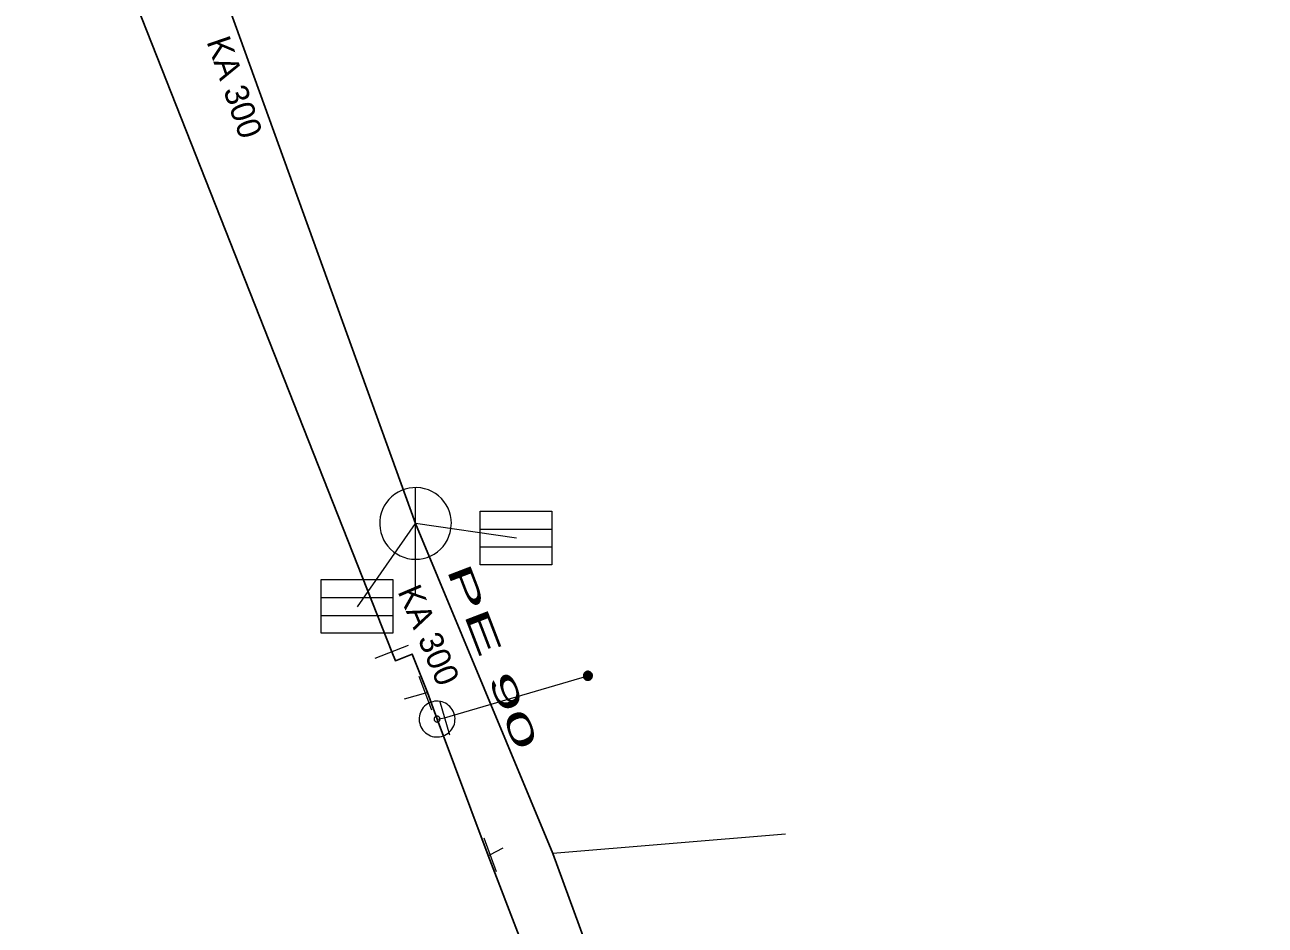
# Model space of a CAD drawing. Extents: x -688432 to -687974, y -973332 to -972704.
# Drawn here: x -688249.47 to -688214.87, y -972930.31 to -972905.19 of the extents above; entities that cross this region are included whole.
import ezdxf
from ezdxf.enums import TextEntityAlignment as Align

# ---------------------------------------------------------------- set-up
doc = ezdxf.new("R2010")
doc.units = 0
doc.header["$LTSCALE"] = 0.27
for name, color, linetype, lineweight in [('1', 7, 'Continuous', 25), ('11', 7, 'Continuous', 13), ('13', 7, 'Continuous', 13), ('14', 7, 'Continuous', 25), ('17', 7, 'Continuous', 25), ('22', 7, 'Continuous', 13), ('34', 7, 'Continuous', 13), ('47', 7, 'Continuous', 13), ('9', 7, 'Continuous', 13)]:
    doc.layers.add(name, color=color, linetype=linetype, lineweight=lineweight)

msp = doc.modelspace()

# ---------------------------------------------------------------- linework, layer by layer
at = {"layer": '11'}
for p, q in [((-688240.193, -972921.423), (-688238.57, -972919.1)), ((-688235.756, -972919.514), (-688238.57, -972919.1)), ((-688228.249, -972927.769), (-688234.738, -972928.309))]:
    msp.add_line(p, q, dxfattribs=at)
at = {"layer": '13'}
for p, q in [((-688238.292, -972923.84), (-688238.89, -972924)), ((-688236.494, -972928.343), (-688236.129, -972928.149))]:
    msp.add_line(p, q, dxfattribs=at)
at = {"layer": '14'}
msp.add_line((-688238.57, -972919.1), (-688245.539, -972899.801), dxfattribs=at)
at = {"layer": '14', "lineweight": 13}
for p, q in [((-688238.239, -972923.82), (-688238.292, -972923.84)), ((-688236.539, -972928.36), (-688236.494, -972928.343))]:
    msp.add_line(p, q, dxfattribs=at)
at = {"layer": '14'}
msp.add_lwpolyline([(-688232.039, -972935.68), (-688234.738, -972928.309), (-688238.57, -972919.1)], dxfattribs=at)
at = {"layer": '14', "lineweight": 13}
msp.add_lwpolyline([(-688237.969, -972924.559), (-688237.76, -972924.52), (-688233.76, -972923.35)], dxfattribs=at)
at = {"layer": '17'}
for points in [[(-688239.23, -972922.68), (-688246.472, -972904.316), (-688249.47, -972882.184)], [(-688237.969, -972924.559), (-688238.239, -972923.82), (-688238.659, -972922.743), (-688239.129, -972922.93), (-688239.23, -972922.68)], [(-688167.42, -973053.719), (-688175.149, -973043.51), (-688175.68, -973042.93), (-688189.18, -973023.62), (-688194.239, -973015.879), (-688201.127, -973004.614), (-688201.64, -973003.76), (-688208.85, -972990.539), (-688214.25, -972980.469), (-688218.649, -972971.53), (-688218.84, -972971.059), (-688222.559, -972963.52), (-688226.68, -972954.28), (-688230.09, -972945.899), (-688231.09, -972942.949), (-688233.719, -972935.719), (-688236.539, -972928.36), (-688237.969, -972924.559)]]:
    msp.add_lwpolyline(points, dxfattribs=at)
at = {"layer": '22'}
for p, q in [((-688238.57, -972921.1), (-688238.569, -972918.1)), ((-688236.767, -972919.257), (-688234.767, -972919.257)), ((-688236.767, -972919.757), (-688234.767, -972919.757)), ((-688241.204, -972921.166), (-688239.204, -972921.166)), ((-688241.204, -972921.666), (-688239.204, -972921.666))]:
    msp.add_line(p, q, dxfattribs=at)
for points in [[(-688237.57, -972919.1), (-688237.575, -972918.991), (-688237.593, -972918.883), (-688237.623, -972918.777), (-688237.663, -972918.676), (-688237.715, -972918.579), (-688237.777, -972918.489), (-688237.849, -972918.406), (-688237.929, -972918.332), (-688238.017, -972918.266), (-688238.111, -972918.211), (-688238.211, -972918.166), (-688238.316, -972918.133), (-688238.423, -972918.111), (-688238.532, -972918.101), (-688238.642, -972918.103), (-688238.75, -972918.117), (-688238.857, -972918.142), (-688238.96, -972918.179), (-688239.058, -972918.228), (-688239.15, -972918.286), (-688239.236, -972918.355), (-688239.313, -972918.432), (-688239.382, -972918.518), (-688239.441, -972918.61), (-688239.489, -972918.708), (-688239.526, -972918.811), (-688239.552, -972918.918), (-688239.566, -972919.026), (-688239.569, -972919.136), (-688239.559, -972919.245), (-688239.538, -972919.352), (-688239.504, -972919.456), (-688239.46, -972919.556), (-688239.405, -972919.651), (-688239.339, -972919.739), (-688239.265, -972919.819), (-688239.182, -972919.891), (-688239.092, -972919.953), (-688238.996, -972920.005), (-688238.894, -972920.046), (-688238.789, -972920.076), (-688238.681, -972920.094), (-688238.571, -972920.1), (-688238.462, -972920.094), (-688238.354, -972920.076), (-688238.249, -972920.047), (-688238.147, -972920.006), (-688238.05, -972919.954), (-688237.96, -972919.892), (-688237.877, -972919.821), (-688237.802, -972919.741), (-688237.737, -972919.653), (-688237.681, -972919.559), (-688237.637, -972919.459), (-688237.603, -972919.355), (-688237.581, -972919.247), (-688237.571, -972919.138)], [(-688236.767, -972918.757), (-688234.767, -972918.757), (-688234.767, -972920.257), (-688236.767, -972920.257)], [(-688241.204, -972920.666), (-688239.204, -972920.666), (-688239.204, -972922.166), (-688241.204, -972922.166)]]:
    msp.add_lwpolyline(points, close=True, dxfattribs=at)
at = {"layer": '34'}
for p, q in [((-688239.694, -972922.863), (-688238.764, -972922.497)), ((-688238.112, -972924.306), (-688238.47, -972923.373)), ((-688237.9, -972924.04), (-688237.62, -972925)), ((-688236.666, -972927.873), (-688236.322, -972928.812))]:
    msp.add_line(p, q, dxfattribs=at)
at = {"layer": '47'}
for points in [[(-688238.14, -972924.089), (-688238.188, -972924.109), (-688238.234, -972924.135), (-688238.276, -972924.165), (-688238.316, -972924.199), (-688238.352, -972924.237), (-688238.383, -972924.28), (-688238.409, -972924.324), (-688238.432, -972924.372), (-688238.449, -972924.421), (-688238.461, -972924.472), (-688238.467, -972924.524), (-688238.468, -972924.577), (-688238.464, -972924.628), (-688238.453, -972924.68), (-688238.438, -972924.73), (-688238.418, -972924.778), (-688238.392, -972924.824), (-688238.362, -972924.867), (-688238.328, -972924.906), (-688238.29, -972924.942), (-688238.247, -972924.973), (-688238.202, -972925), (-688238.155, -972925.022), (-688238.106, -972925.04), (-688238.055, -972925.051), (-688238.003, -972925.057), (-688237.95, -972925.058), (-688237.899, -972925.054), (-688237.847, -972925.043), (-688237.797, -972925.028), (-688237.749, -972925.008), (-688237.703, -972924.982), (-688237.66, -972924.953), (-688237.621, -972924.918), (-688237.585, -972924.88), (-688237.553, -972924.838), (-688237.526, -972924.793), (-688237.504, -972924.746), (-688237.487, -972924.696), (-688237.476, -972924.645), (-688237.47, -972924.593), (-688237.468, -972924.541), (-688237.473, -972924.489), (-688237.484, -972924.437), (-688237.499, -972924.387), (-688237.519, -972924.339), (-688237.545, -972924.293), (-688237.574, -972924.251), (-688237.609, -972924.211), (-688237.647, -972924.175), (-688237.689, -972924.143), (-688237.734, -972924.117), (-688237.781, -972924.095), (-688237.831, -972924.078), (-688237.882, -972924.066), (-688237.934, -972924.06), (-688237.986, -972924.059), (-688238.038, -972924.063), (-688238.09, -972924.074)], [(-688237.997, -972924.481), (-688238.005, -972924.485), (-688238.012, -972924.489), (-688238.019, -972924.494), (-688238.025, -972924.499), (-688238.031, -972924.506), (-688238.036, -972924.513), (-688238.041, -972924.52), (-688238.045, -972924.528), (-688238.047, -972924.536), (-688238.049, -972924.544), (-688238.05, -972924.553), (-688238.05, -972924.562), (-688238.049, -972924.57), (-688238.049, -972924.578), (-688238.046, -972924.587), (-688238.042, -972924.595), (-688238.038, -972924.602), (-688238.033, -972924.609), (-688238.028, -972924.615), (-688238.021, -972924.621), (-688238.014, -972924.626), (-688238.007, -972924.631), (-688237.999, -972924.635), (-688237.991, -972924.638), (-688237.983, -972924.639), (-688237.974, -972924.64), (-688237.965, -972924.64), (-688237.957, -972924.639), (-688237.949, -972924.639), (-688237.94, -972924.636), (-688237.932, -972924.632), (-688237.925, -972924.628), (-688237.918, -972924.623), (-688237.912, -972924.618), (-688237.906, -972924.611), (-688237.9, -972924.605), (-688237.896, -972924.597), (-688237.892, -972924.589), (-688237.889, -972924.581), (-688237.888, -972924.573), (-688237.887, -972924.564), (-688237.887, -972924.555), (-688237.888, -972924.547), (-688237.888, -972924.539), (-688237.891, -972924.53), (-688237.895, -972924.522), (-688237.899, -972924.515), (-688237.904, -972924.508), (-688237.909, -972924.502), (-688237.916, -972924.496), (-688237.922, -972924.49), (-688237.93, -972924.486), (-688237.938, -972924.482), (-688237.946, -972924.48), (-688237.954, -972924.478), (-688237.963, -972924.477), (-688237.972, -972924.477), (-688237.98, -972924.478), (-688237.988, -972924.478)]]:
    msp.add_lwpolyline(points, close=True, dxfattribs=at)
at = {"layer": '9'}
for points in [[(-688233.886, -972923.35), (-688233.886, -972923.363), (-688233.884, -972923.376), (-688233.881, -972923.389), (-688233.876, -972923.401), (-688233.87, -972923.413), (-688233.863, -972923.424), (-688233.855, -972923.434), (-688233.845, -972923.444), (-688233.835, -972923.452), (-688233.824, -972923.459), (-688233.812, -972923.465), (-688233.8, -972923.47), (-688233.787, -972923.473), (-688233.774, -972923.475), (-688233.761, -972923.477), (-688233.748, -972923.476), (-688233.735, -972923.474), (-688233.722, -972923.471), (-688233.71, -972923.466), (-688233.698, -972923.46), (-688233.687, -972923.453), (-688233.677, -972923.445), (-688233.667, -972923.435), (-688233.659, -972923.425), (-688233.652, -972923.414), (-688233.646, -972923.402), (-688233.641, -972923.39), (-688233.638, -972923.377), (-688233.636, -972923.364), (-688233.634, -972923.351), (-688233.635, -972923.338), (-688233.637, -972923.325), (-688233.64, -972923.312), (-688233.645, -972923.3), (-688233.651, -972923.288), (-688233.658, -972923.277), (-688233.666, -972923.267), (-688233.676, -972923.257), (-688233.686, -972923.249), (-688233.697, -972923.242), (-688233.709, -972923.236), (-688233.721, -972923.231), (-688233.734, -972923.228), (-688233.747, -972923.226), (-688233.76, -972923.225), (-688233.773, -972923.225), (-688233.786, -972923.227), (-688233.799, -972923.23), (-688233.811, -972923.235), (-688233.823, -972923.241), (-688233.834, -972923.248), (-688233.844, -972923.256), (-688233.854, -972923.266), (-688233.862, -972923.276), (-688233.869, -972923.287), (-688233.875, -972923.299), (-688233.88, -972923.311), (-688233.883, -972923.324), (-688233.885, -972923.337)], [(-688233.866, -972923.35), (-688233.867, -972923.361), (-688233.865, -972923.372), (-688233.862, -972923.383), (-688233.858, -972923.393), (-688233.853, -972923.403), (-688233.847, -972923.412), (-688233.84, -972923.421), (-688233.832, -972923.429), (-688233.823, -972923.436), (-688233.814, -972923.442), (-688233.804, -972923.447), (-688233.794, -972923.451), (-688233.783, -972923.454), (-688233.772, -972923.457), (-688233.761, -972923.457), (-688233.75, -972923.457), (-688233.739, -972923.455), (-688233.728, -972923.452), (-688233.718, -972923.448), (-688233.708, -972923.443), (-688233.699, -972923.437), (-688233.69, -972923.43), (-688233.682, -972923.422), (-688233.675, -972923.413), (-688233.669, -972923.404), (-688233.664, -972923.394), (-688233.66, -972923.384), (-688233.657, -972923.373), (-688233.655, -972923.362), (-688233.654, -972923.351), (-688233.654, -972923.34), (-688233.656, -972923.329), (-688233.659, -972923.318), (-688233.663, -972923.308), (-688233.668, -972923.298), (-688233.674, -972923.289), (-688233.681, -972923.28), (-688233.689, -972923.272), (-688233.698, -972923.265), (-688233.707, -972923.259), (-688233.717, -972923.254), (-688233.727, -972923.25), (-688233.738, -972923.247), (-688233.749, -972923.245), (-688233.76, -972923.245), (-688233.771, -972923.244), (-688233.782, -972923.246), (-688233.793, -972923.249), (-688233.803, -972923.253), (-688233.813, -972923.258), (-688233.822, -972923.264), (-688233.831, -972923.271), (-688233.839, -972923.279), (-688233.846, -972923.288), (-688233.852, -972923.297), (-688233.857, -972923.307), (-688233.861, -972923.317), (-688233.864, -972923.328), (-688233.866, -972923.339)], [(-688233.847, -972923.35), (-688233.847, -972923.359), (-688233.846, -972923.368), (-688233.843, -972923.377), (-688233.84, -972923.385), (-688233.836, -972923.393), (-688233.831, -972923.401), (-688233.825, -972923.408), (-688233.819, -972923.414), (-688233.812, -972923.42), (-688233.804, -972923.425), (-688233.796, -972923.429), (-688233.788, -972923.432), (-688233.779, -972923.435), (-688233.77, -972923.436), (-688233.761, -972923.438), (-688233.752, -972923.437), (-688233.743, -972923.436), (-688233.734, -972923.433), (-688233.726, -972923.43), (-688233.718, -972923.426), (-688233.71, -972923.421), (-688233.703, -972923.415), (-688233.697, -972923.409), (-688233.691, -972923.402), (-688233.686, -972923.394), (-688233.682, -972923.386), (-688233.679, -972923.378), (-688233.676, -972923.369), (-688233.675, -972923.36), (-688233.673, -972923.351), (-688233.674, -972923.342), (-688233.675, -972923.333), (-688233.678, -972923.324), (-688233.681, -972923.316), (-688233.685, -972923.308), (-688233.69, -972923.3), (-688233.696, -972923.293), (-688233.702, -972923.287), (-688233.709, -972923.281), (-688233.717, -972923.276), (-688233.725, -972923.272), (-688233.733, -972923.269), (-688233.742, -972923.266), (-688233.751, -972923.265), (-688233.76, -972923.264), (-688233.769, -972923.264), (-688233.778, -972923.265), (-688233.787, -972923.268), (-688233.795, -972923.271), (-688233.803, -972923.275), (-688233.811, -972923.28), (-688233.818, -972923.286), (-688233.824, -972923.292), (-688233.83, -972923.299), (-688233.835, -972923.307), (-688233.839, -972923.315), (-688233.842, -972923.323), (-688233.845, -972923.332), (-688233.846, -972923.341)], [(-688233.827, -972923.35), (-688233.827, -972923.357), (-688233.826, -972923.364), (-688233.825, -972923.371), (-688233.822, -972923.377), (-688233.819, -972923.383), (-688233.815, -972923.389), (-688233.811, -972923.395), (-688233.806, -972923.4), (-688233.8, -972923.404), (-688233.794, -972923.408), (-688233.788, -972923.411), (-688233.782, -972923.414), (-688233.775, -972923.415), (-688233.768, -972923.418), (-688233.761, -972923.418), (-688233.754, -972923.418), (-688233.747, -972923.416), (-688233.74, -972923.415), (-688233.734, -972923.412), (-688233.727, -972923.409), (-688233.722, -972923.405), (-688233.716, -972923.401), (-688233.711, -972923.396), (-688233.707, -972923.39), (-688233.703, -972923.384), (-688233.7, -972923.378), (-688233.697, -972923.372), (-688233.695, -972923.365), (-688233.694, -972923.358), (-688233.693, -972923.351), (-688233.693, -972923.344), (-688233.694, -972923.337), (-688233.696, -972923.33), (-688233.699, -972923.324), (-688233.702, -972923.317), (-688233.706, -972923.312), (-688233.71, -972923.306), (-688233.715, -972923.301), (-688233.721, -972923.297), (-688233.726, -972923.293), (-688233.733, -972923.29), (-688233.739, -972923.287), (-688233.746, -972923.285), (-688233.753, -972923.284), (-688233.76, -972923.284), (-688233.767, -972923.284), (-688233.774, -972923.284), (-688233.781, -972923.286), (-688233.787, -972923.289), (-688233.793, -972923.292), (-688233.799, -972923.296), (-688233.805, -972923.3), (-688233.81, -972923.305), (-688233.814, -972923.311), (-688233.818, -972923.316), (-688233.821, -972923.323), (-688233.824, -972923.329), (-688233.825, -972923.336), (-688233.827, -972923.343)], [(-688233.807, -972923.35), (-688233.807, -972923.355), (-688233.807, -972923.36), (-688233.806, -972923.365), (-688233.804, -972923.369), (-688233.802, -972923.374), (-688233.799, -972923.378), (-688233.796, -972923.381), (-688233.792, -972923.385), (-688233.789, -972923.388), (-688233.785, -972923.391), (-688233.78, -972923.393), (-688233.776, -972923.395), (-688233.771, -972923.396), (-688233.766, -972923.398), (-688233.761, -972923.398), (-688233.756, -972923.398), (-688233.751, -972923.397), (-688233.746, -972923.396), (-688233.742, -972923.394), (-688233.737, -972923.392), (-688233.733, -972923.389), (-688233.729, -972923.386), (-688233.726, -972923.382), (-688233.723, -972923.379), (-688233.72, -972923.375), (-688233.718, -972923.37), (-688233.716, -972923.366), (-688233.715, -972923.361), (-688233.714, -972923.356), (-688233.713, -972923.351), (-688233.713, -972923.346), (-688233.714, -972923.341), (-688233.715, -972923.336), (-688233.717, -972923.332), (-688233.719, -972923.327), (-688233.722, -972923.323), (-688233.725, -972923.319), (-688233.728, -972923.316), (-688233.732, -972923.313), (-688233.736, -972923.31), (-688233.741, -972923.308), (-688233.745, -972923.306), (-688233.75, -972923.305), (-688233.755, -972923.304), (-688233.76, -972923.304), (-688233.765, -972923.304), (-688233.77, -972923.305), (-688233.775, -972923.305), (-688233.779, -972923.307), (-688233.784, -972923.309), (-688233.788, -972923.312), (-688233.791, -972923.315), (-688233.795, -972923.318), (-688233.798, -972923.322), (-688233.801, -972923.326), (-688233.803, -972923.331), (-688233.805, -972923.335), (-688233.806, -972923.34), (-688233.807, -972923.345)], [(-688233.787, -972923.35), (-688233.787, -972923.353), (-688233.788, -972923.356), (-688233.787, -972923.358), (-688233.786, -972923.361), (-688233.785, -972923.364), (-688233.783, -972923.366), (-688233.781, -972923.368), (-688233.779, -972923.37), (-688233.777, -972923.372), (-688233.775, -972923.374), (-688233.772, -972923.376), (-688233.769, -972923.377), (-688233.767, -972923.377), (-688233.764, -972923.378), (-688233.761, -972923.378), (-688233.758, -972923.378), (-688233.755, -972923.378), (-688233.752, -972923.377), (-688233.75, -972923.376), (-688233.747, -972923.375), (-688233.745, -972923.373), (-688233.742, -972923.371), (-688233.74, -972923.369), (-688233.739, -972923.367), (-688233.737, -972923.365), (-688233.736, -972923.362), (-688233.734, -972923.359), (-688233.734, -972923.357), (-688233.733, -972923.354), (-688233.732, -972923.351), (-688233.733, -972923.348), (-688233.733, -972923.345), (-688233.734, -972923.342), (-688233.735, -972923.34), (-688233.736, -972923.337), (-688233.738, -972923.335), (-688233.739, -972923.332), (-688233.741, -972923.33), (-688233.744, -972923.329), (-688233.746, -972923.327), (-688233.749, -972923.326), (-688233.751, -972923.325), (-688233.754, -972923.324), (-688233.757, -972923.324), (-688233.76, -972923.323), (-688233.763, -972923.324), (-688233.766, -972923.323), (-688233.768, -972923.325), (-688233.771, -972923.325), (-688233.774, -972923.326), (-688233.776, -972923.328), (-688233.778, -972923.329), (-688233.78, -972923.331), (-688233.782, -972923.334), (-688233.784, -972923.336), (-688233.785, -972923.339), (-688233.786, -972923.341), (-688233.787, -972923.344), (-688233.787, -972923.347)], [(-688233.768, -972923.35), (-688233.768, -972923.352), (-688233.768, -972923.352), (-688233.767, -972923.352), (-688233.767, -972923.354), (-688233.768, -972923.355), (-688233.766, -972923.355), (-688233.766, -972923.355), (-688233.766, -972923.357), (-688233.766, -972923.357), (-688233.765, -972923.358), (-688233.763, -972923.358), (-688233.763, -972923.358), (-688233.763, -972923.359), (-688233.761, -972923.359), (-688233.761, -972923.359), (-688233.76, -972923.359), (-688233.759, -972923.359), (-688233.759, -972923.358), (-688233.758, -972923.358), (-688233.756, -972923.358), (-688233.756, -972923.357), (-688233.756, -972923.357), (-688233.755, -972923.356), (-688233.755, -972923.356), (-688233.753, -972923.355), (-688233.753, -972923.354), (-688233.752, -972923.353), (-688233.752, -972923.353), (-688233.752, -972923.352), (-688233.752, -972923.351), (-688233.752, -972923.35), (-688233.752, -972923.349), (-688233.752, -972923.349), (-688233.753, -972923.348), (-688233.753, -972923.347), (-688233.754, -972923.346), (-688233.754, -972923.346), (-688233.755, -972923.345), (-688233.755, -972923.345), (-688233.756, -972923.344), (-688233.757, -972923.344), (-688233.758, -972923.343), (-688233.758, -972923.343), (-688233.759, -972923.343), (-688233.76, -972923.343), (-688233.761, -972923.343), (-688233.762, -972923.343), (-688233.762, -972923.343), (-688233.763, -972923.344), (-688233.764, -972923.343), (-688233.765, -972923.345), (-688233.765, -972923.345), (-688233.766, -972923.345), (-688233.766, -972923.345), (-688233.767, -972923.347), (-688233.767, -972923.348), (-688233.767, -972923.349), (-688233.768, -972923.349), (-688233.768, -972923.35)]]:
    msp.add_lwpolyline(points, close=True, dxfattribs=at)

# ---------------------------------------------------------------- texts
at = {"layer": '1'}
for rotation, p in [(289, (-688243.9304, -972907.0383)), (289, (-688243.9304, -972907.0383)), (289, (-688243.9304, -972907.0383)), (289, (-688243.9304, -972907.0383)), (289, (-688243.9304, -972907.0383)), (293, (-688238.506, -972922.3436)), (293, (-688238.506, -972922.3436)), (293, (-688238.506, -972922.3436)), (293, (-688238.506, -972922.3436)), (293, (-688238.506, -972922.3436))]:
    msp.add_text('KA 300', height=0.6667, rotation=rotation, dxfattribs=at).set_placement(p, align=Align.CENTER)
at = {"layer": '1', "width": 2.25}
msp.add_text('PE 90 ', height=0.6667, rotation=291, dxfattribs=at).set_placement((-688236.636, -972923.1945), align=Align.CENTER)
msp.add_text('PE 90 ', height=0.6667, rotation=291, dxfattribs=at).set_placement((-688236.636, -972923.1945), align=Align.CENTER)
msp.add_text('PE 90 ', height=0.6667, rotation=291, dxfattribs=at).set_placement((-688236.636, -972923.1945), align=Align.CENTER)
msp.add_text('PE 90 ', height=0.6667, rotation=291, dxfattribs=at).set_placement((-688236.636, -972923.1945), align=Align.CENTER)
msp.add_text('PE 90 ', height=0.6667, rotation=291, dxfattribs=at).set_placement((-688236.636, -972923.1945), align=Align.CENTER)

doc.saveas('drawing.dxf')
